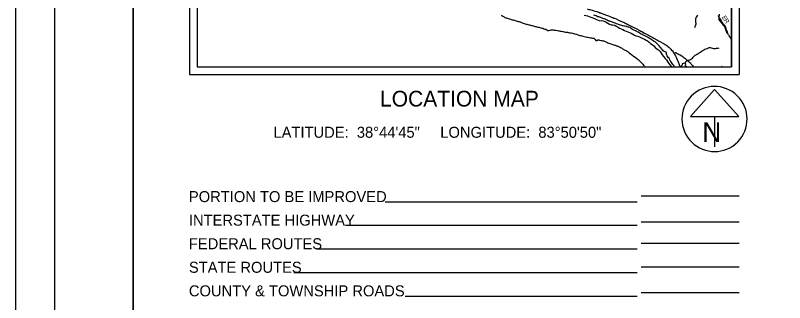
# Model space of a CAD drawing. Extents: x 0 to 34, y 0 to 22.
# Drawn here: x 0 to 9.79, y 11.1 to 14.75 of the extents above; entities that cross this region are included whole.
import ezdxf

# ---------------------------------------------------------------- set-up
doc = ezdxf.new("R2010")
doc.units = 0
for name, color, linetype in [('Default', 7, 'Continuous'), ('GM_X_Major_River', 7, 'Continuous'), ('GM_X_Minor_River', 7, 'Continuous'), ('GM_X_Township_Road', 7, 'Continuous'), ('GM_X_Township_Road_Text', 7, 'Continuous'), ('GM_X_US_Route', 7, 'Continuous'), ('SH_Border', 7, 'Continuous'), ('SH_Cut_Line', 7, 'Continuous'), ('SH_Data', 7, 'Continuous'), ('SH_Text', 7, 'Continuous')]:
    doc.layers.add(name, color=color, linetype=linetype)

msp = doc.modelspace()

# ---------------------------------------------------------------- linework, layer by layer
at = {"layer": 'Default'}
msp.add_lwpolyline([(7.2409, 14.7567), (7.2605, 14.7513), (7.2834, 14.7475), (7.3046, 14.7393), (7.3244, 14.7309), (7.3479, 14.7233), (7.3703, 14.7143), (7.3952, 14.7015), (7.4163, 14.6918), (7.4385, 14.6851), (7.4584, 14.687), (7.4818, 14.6833), (7.501, 14.6756), (7.52, 14.667), (7.5406, 14.6542), (7.5611, 14.6406), (7.5821, 14.635), (7.603, 14.6335), (7.6287, 14.628), (7.6487, 14.6172), (7.6713, 14.6052), (7.6906, 14.5923), (7.7101, 14.5815), (7.7299, 14.5723), (7.752, 14.5624), (7.7959, 14.545), (7.8174, 14.5359), (7.8368, 14.5262), (7.8575, 14.5129), (7.8787, 14.5014), (7.8985, 14.4932), (7.9208, 14.4887), (7.942, 14.4801), (7.9627, 14.471), (7.9861, 14.4585), (8.0071, 14.449), (8.0265, 14.44), (8.0454, 14.4281), (8.0661, 14.4119), (8.0855, 14.397), (8.1063, 14.3826), (8.1264, 14.3655), (8.1445, 14.3461), (8.1649, 14.328), (8.186, 14.314), (8.206, 14.2944), (8.2209, 14.2742), (8.2341, 14.2531), (8.249, 14.2305), (8.2693, 14.2063), (8.2877, 14.1863), (8.3015, 14.1672), (8.3143, 14.1469), (8.3277, 14.1258), (8.3467, 14.101), (8.3479, 14.0996), (9.1142, 14.0996), (9.1142, 17.7402)], dxfattribs=at)
at = {"layer": 'GM_X_Major_River'}
for points in [[(6.1819, 14.7546), (6.1936, 14.7506), (6.2045, 14.7444), (6.2195, 14.7348), (6.2316, 14.7286), (6.2414, 14.7243), (6.2512, 14.7211), (6.261, 14.7187), (6.2735, 14.7133), (6.2893, 14.7082), (6.2995, 14.7054), (6.3124, 14.7022), (6.3237, 14.6987), (6.3339, 14.6955), (6.3479, 14.6916), (6.3607, 14.688), (6.3743, 14.6833), (6.3872, 14.6793), (6.3977, 14.6762), (6.4102, 14.6741)], [(7.9535, 14.5239), (7.938, 14.5324), (7.9275, 14.5382), (7.9154, 14.5448), (7.9026, 14.5526), (7.8925, 14.558), (7.8826, 14.5619), (7.8698, 14.5647), (7.8562, 14.5736), (7.8427, 14.5844), (7.8318, 14.5917), (7.8201, 14.5987), (7.81, 14.6026), (7.8001, 14.6058), (7.7869, 14.609), (7.7763, 14.611), (7.7631, 14.6149), (7.751, 14.6181), (7.7374, 14.6201), (7.7272, 14.6222), (7.7174, 14.6246), (7.7015, 14.6289), (7.6909, 14.6321), (7.6769, 14.6375), (7.6668, 14.6415), (7.6528, 14.6462), (7.6426, 14.6497), (7.632, 14.6536), (7.6207, 14.6576), (7.609, 14.6619), (7.5988, 14.6662), (7.589, 14.6708), (7.5766, 14.6755), (7.5667, 14.6783), (7.5554, 14.6815), (7.5445, 14.6858), (7.5309, 14.6916), (7.5207, 14.697), (7.506, 14.7037), (7.4928, 14.7088), (7.4785, 14.7158), (7.4672, 14.7204), (7.4509, 14.7271), (7.4377, 14.731), (7.4271, 14.7334), (7.4147, 14.7359), (7.403, 14.7402), (7.3905, 14.746), (7.3766, 14.7515), (7.3637, 14.7554)], [(6.4102, 14.6741), (6.4238, 14.6709), (6.4495, 14.6608), (6.4631, 14.6549), (6.4763, 14.6498), (6.4865, 14.6471), (6.4997, 14.6435), (6.5099, 14.6407), (6.5227, 14.6375), (6.5333, 14.6351), (6.5447, 14.6327), (6.5564, 14.6299), (6.5681, 14.6268), (6.5787, 14.6244), (6.59, 14.6212), (6.6032, 14.6176), (6.6161, 14.6141), (6.6259, 14.6113), (6.638, 14.6081), (6.6508, 14.6046), (6.6614, 14.6018), (6.6739, 14.5994), (6.6886, 14.5961), (6.7003, 14.593), (6.712, 14.5894), (6.7271, 14.5843), (6.7396, 14.5804), (6.7524, 14.5764), (6.7649, 14.5706), (6.7777, 14.5629), (6.7913, 14.5597), (6.8046, 14.5663), (6.8191, 14.5707), (6.8312, 14.5698), (6.8441, 14.5685), (6.8562, 14.5669), (6.8698, 14.5652), (6.8796, 14.564), (6.8997, 14.5595), (6.911, 14.5571), (6.922, 14.5551), (6.9329, 14.5535), (6.9481, 14.5514), (6.9621, 14.5493), (6.9723, 14.5473), (6.9863, 14.5441), (7.0033, 14.5413), (7.0154, 14.5396), (7.0264, 14.538), (7.0392, 14.5352), (7.0521, 14.5331), (7.0634, 14.5315), (7.0744, 14.5298), (7.0895, 14.5266), (7.105, 14.5234), (7.1167, 14.5202), (7.1266, 14.5175), (7.142, 14.5127), (7.1598, 14.5072), (7.1707, 14.5037), (7.1855, 14.4997), (7.1987, 14.4961), (7.2104, 14.493), (7.2217, 14.4902), (7.238, 14.4866), (7.255, 14.4822), (7.2747, 14.4774), (7.2871, 14.4746), (7.303, 14.4721), (7.3181, 14.4693), (7.3321, 14.4669), (7.3473, 14.464), (7.3609, 14.462), (7.3707, 14.4569), (7.38, 14.4454), (7.3886, 14.4351), (7.4015, 14.4353), (7.4152, 14.4435), (7.4251, 14.4423), (7.4353, 14.4395), (7.4496, 14.4359), (7.4644, 14.4335), (7.4784, 14.431), (7.4882, 14.4283), (7.4988, 14.4247), (7.5139, 14.4185), (7.5263, 14.4123), (7.5395, 14.4064), (7.5535, 14.4013), (7.5678, 14.3958), (7.5799, 14.3915), (7.5912, 14.388), (7.6041, 14.3836), (7.6143, 14.3805), (7.6278, 14.3762), (7.6392, 14.3726), (7.6505, 14.3679), (7.6614, 14.364), (7.675, 14.3585), (7.689, 14.3523), (7.7025, 14.3461)], [(8.3892, 14.0996), (8.3865, 14.1037), (8.3787, 14.1155), (8.369, 14.1285), (8.3604, 14.1408), (8.3496, 14.155), (8.3421, 14.1645), (8.3358, 14.1767), (8.331, 14.1889), (8.3247, 14.2027), (8.3138, 14.215), (8.3045, 14.2249), (8.2955, 14.2372), (8.2896, 14.249), (8.2878, 14.2585), (8.2861, 14.2715), (8.2813, 14.2837), (8.2692, 14.291), (8.2567, 14.2919), (8.244, 14.3023), (8.2369, 14.3141), (8.2268, 14.3257), (8.2144, 14.3387), (8.2047, 14.351), (8.1976, 14.3617), (8.1894, 14.372), (8.1778, 14.3839), (8.1643, 14.397), (8.1523, 14.407), (8.141, 14.4151), (8.1289, 14.4228), (8.1161, 14.4306), (8.1037, 14.4379), (8.0928, 14.4452), (8.0815, 14.4533), (8.0687, 14.4618), (8.0575, 14.4688), (8.0454, 14.4758), (8.0292, 14.4843), (8.0013, 14.4987), (7.9908, 14.5034), (7.9791, 14.5096), (7.9667, 14.5165), (7.9535, 14.5239)], [(7.7025, 14.3461), (7.7146, 14.3395), (7.7262, 14.3299), (7.7387, 14.3221), (7.7496, 14.3163), (7.7605, 14.3124), (7.7722, 14.3062), (7.7831, 14.2988), (7.7993, 14.288), (7.8113, 14.2788), (7.8301, 14.263), (7.8421, 14.2537), (7.8519, 14.2468), (7.8651, 14.2383), (7.8797, 14.2275), (7.8899, 14.2198), (7.9038, 14.2094), (7.9158, 14.199), (7.9255, 14.1905), (7.9394, 14.1782), (7.9507, 14.1663), (7.9604, 14.1571), (7.9754, 14.1433), (7.9866, 14.131), (7.9964, 14.1206), (8.0068, 14.1061), (8.0113, 14.0996)]]:
    msp.add_lwpolyline(points, dxfattribs=at)
at = {"layer": 'GM_X_Minor_River'}
msp.add_line((8.9886, 14.0996), (8.9952, 14.1065), dxfattribs=at)
for points in [[(7.3861, 14.7477), (7.3929, 14.7618)], [(8.6798, 14.7552), (8.6732, 14.7424), (8.6658, 14.7303), (8.6599, 14.719), (8.6567, 14.7084), (8.6546, 14.6944), (8.6556, 14.6807), (8.6573, 14.6678), (8.6586, 14.6545), (8.6588, 14.6438), (8.6583, 14.6309), (8.6543, 14.6173), (8.6492, 14.6068), (8.6433, 14.5935)], [(8.9557, 14.7683), (8.9558, 14.7535), (8.9549, 14.7425), (8.954, 14.7311), (8.9541, 14.7167), (8.9544, 14.7049), (8.9576, 14.6934), (8.965, 14.6827), (8.9766, 14.6708), (8.9859, 14.6573), (8.9959, 14.6443), (9.0101, 14.6296), (9.0239, 14.6131), (9.0313, 14.5997), (9.0361, 14.5886), (9.0382, 14.5783), (9.0399, 14.5681), (9.0447, 14.5539), (9.0494, 14.541), (9.056, 14.5287)], [(8.5253, 14.1464), (8.5342, 14.166), (8.545, 14.1761), (8.5587, 14.1816), (8.5716, 14.1848), (8.5831, 14.1881), (8.5941, 14.1932), (8.606, 14.1999), (8.6175, 14.2085), (8.6276, 14.222), (8.6384, 14.2347), (8.6522, 14.2463), (8.6625, 14.2522), (8.6751, 14.2589), (8.6847, 14.2637), (8.6969, 14.2726), (8.7084, 14.2801), (8.718, 14.2864), (8.7279, 14.2919), (8.7421, 14.3004), (8.7559, 14.309), (8.7654, 14.3145), (8.7773, 14.3216), (8.7903, 14.3263), (8.8067, 14.3318), (8.8212, 14.3388), (8.8318, 14.3428), (8.8433, 14.3453), (8.8576, 14.3424), (8.8712, 14.3366), (8.8848, 14.3337), (8.8977, 14.3328), (8.9113, 14.3333), (8.9235, 14.3347), (8.9341, 14.3364), (8.9444, 14.3385), (8.9577, 14.3418)], [(8.5452, 14.0996), (8.5427, 14.1013), (8.5296, 14.1084), (8.5274, 14.1194), (8.5315, 14.1338), (8.5267, 14.1467), (8.5008, 14.1403), (8.4883, 14.1386), (8.4858, 14.1257), (8.4845, 14.1162), (8.4752, 14.1027), (8.4698, 14.0996)]]:
    msp.add_lwpolyline(points, dxfattribs=at)
at = {"layer": 'GM_X_Township_Road'}
for points in [[(9.1142, 14.4493), (9.1125, 14.4514), (9.0974, 14.4744), (9.086, 14.4914), (9.0787, 14.503), (9.0763, 14.5073), (9.0721, 14.5156), (9.0699, 14.5207), (9.0681, 14.526), (9.0656, 14.5356), (9.0642, 14.541), (9.0628, 14.5451), (9.0614, 14.5492), (9.059, 14.5549), (9.0557, 14.5616), (9.0518, 14.5694), (9.0489, 14.5756), (9.047, 14.5809), (9.0459, 14.5844), (9.0449, 14.588), (9.0413, 14.6037), (9.0404, 14.6074), (9.0389, 14.6111), (9.0371, 14.6144), (9.0347, 14.618), (9.0312, 14.6224), (9.0262, 14.6279), (9.02, 14.634), (9.0129, 14.641), (9.0088, 14.6456), (9.0054, 14.65), (9.0023, 14.6547), (8.9986, 14.6611), (8.9934, 14.671), (8.9886, 14.6797), (8.9858, 14.6845), (8.9789, 14.697), (8.9714, 14.7105), (8.9656, 14.7199), (8.9627, 14.7239), (8.9595, 14.728), (8.9551, 14.7338), (8.9523, 14.7386), (8.9511, 14.7421), (8.9504, 14.7445), (8.9496, 14.7494), (8.9492, 14.7543)], [(8.6353, 14.0996), (8.6289, 14.1057), (8.6218, 14.1126), (8.6091, 14.1253), (8.6011, 14.1331), (8.595, 14.1393), (8.5826, 14.1514), (8.5716, 14.1623), (8.5521, 14.1805), (8.5439, 14.188), (8.5332, 14.1974), (8.5094, 14.2154), (8.4937, 14.2255), (8.4616, 14.2456), (8.4499, 14.2526), (8.4376, 14.2599), (8.4202, 14.2704), (8.4149, 14.2738), (8.4097, 14.2764), (8.4042, 14.2779), (8.402, 14.2778), (8.3995, 14.2765), (8.395, 14.2739), (8.3854, 14.2685)]]:
    msp.add_lwpolyline(points, dxfattribs=at)
at = {"layer": 'GM_X_US_Route'}
for points in [[(7.281, 14.8353), (7.287, 14.8339), (7.3002, 14.8304), (7.312, 14.8274), (7.341, 14.8194), (7.3543, 14.8155), (7.3744, 14.8094), (7.3999, 14.8016), (7.4189, 14.7956), (7.4248, 14.7937), (7.44, 14.7883), (7.4482, 14.7852), (7.4598, 14.7807), (7.4754, 14.7747), (7.5004, 14.7652), (7.5195, 14.7581), (7.5482, 14.7475), (7.5882, 14.7321), (7.6049, 14.7254), (7.6165, 14.7204)], [(7.6165, 14.7204), (7.6209, 14.7185), (7.6255, 14.7165)], [(7.6255, 14.7165), (7.6449, 14.7082), (7.6755, 14.6945), (7.7377, 14.6661), (7.747, 14.6617)], [(7.747, 14.6617), (7.7489, 14.6608), (7.7634, 14.6539)], [(7.7634, 14.6539), (7.7725, 14.6496), (7.7949, 14.6388), (7.8394, 14.6168), (7.871, 14.6008), (7.9013, 14.5849), (7.9083, 14.5812)], [(7.9083, 14.5812), (7.9396, 14.5643), (7.9608, 14.553)], [(7.9608, 14.553), (7.9715, 14.5474), (8.0053, 14.529), (8.0581, 14.5), (8.0729, 14.4921), (8.1032, 14.4762), (8.125, 14.4642), (8.1645, 14.4434), (8.1864, 14.4316), (8.2099, 14.4189), (8.2414, 14.4013), (8.257, 14.3922), (8.2702, 14.384), (8.2806, 14.3771), (8.2922, 14.3687), (8.3055, 14.3584), (8.3151, 14.3504), (8.3238, 14.3425), (8.3337, 14.333), (8.3429, 14.3231), (8.3519, 14.3128), (8.3617, 14.3008), (8.3703, 14.2895), (8.3782, 14.2785), (8.3854, 14.2685)], [(8.3854, 14.2685), (8.395, 14.2513), (8.4025, 14.2375), (8.4101, 14.2221), (8.4155, 14.2101), (8.4276, 14.1814), (8.4352, 14.1625), (8.4482, 14.1305), (8.4612, 14.0996)]]:
    msp.add_lwpolyline(points, dxfattribs=at)
at = {"layer": 'SH_Border'}
for points in [[(0.5, 21.5), (1.5, 21.5), (1.5, 0.5), (0.5, 0.5)], [(1.5, 21.5), (33.5, 21.5), (33.5, 0.5), (1.5, 0.5)]]:
    msp.add_lwpolyline(points, close=True, dxfattribs=at)
at = {"layer": 'SH_Cut_Line'}
msp.add_lwpolyline([(0, 0), (34, 0), (34, 22), (0, 22)], close=True, dxfattribs=at)
msp.add_lwpolyline([(7.2409, 14.7567), (7.2605, 14.7513), (7.2834, 14.7475), (7.3046, 14.7393), (7.3244, 14.7309), (7.3479, 14.7233), (7.3703, 14.7143), (7.3952, 14.7015), (7.4163, 14.6918), (7.4385, 14.6851), (7.4584, 14.687), (7.4818, 14.6833), (7.501, 14.6756), (7.52, 14.667), (7.5406, 14.6542), (7.5611, 14.6406), (7.5821, 14.635), (7.603, 14.6335), (7.6287, 14.628), (7.6487, 14.6172), (7.6713, 14.6052), (7.6906, 14.5923), (7.7101, 14.5815), (7.7299, 14.5723), (7.752, 14.5624), (7.7959, 14.545), (7.8174, 14.5359), (7.8368, 14.5262), (7.8575, 14.5129), (7.8787, 14.5014), (7.8985, 14.4932), (7.9208, 14.4887), (7.942, 14.4801), (7.9627, 14.471), (7.9861, 14.4585), (8.0071, 14.449), (8.0265, 14.44), (8.0454, 14.4281), (8.0661, 14.4119), (8.0855, 14.397), (8.1063, 14.3826), (8.1264, 14.3655), (8.1445, 14.3461), (8.1649, 14.328), (8.186, 14.314), (8.206, 14.2944), (8.2209, 14.2742), (8.2341, 14.2531), (8.249, 14.2305), (8.2693, 14.2063), (8.2877, 14.1863), (8.3015, 14.1672), (8.3143, 14.1469), (8.3277, 14.1258), (8.3467, 14.101), (8.3479, 14.0996), (9.1142, 14.0996), (9.1142, 20.8996)], dxfattribs=at)
at = {"layer": 'SH_Data'}
for p, q in [((2.2142, 20.9996), (2.2142, 13.9996)), ((9.2142, 20.9996), (9.2142, 13.9996)), ((2.3142, 20.8996), (2.3142, 14.0996)), ((9.1142, 20.8996), (9.1142, 14.0996)), ((2.3142, 14.0996), (9.1142, 14.0996)), ((2.3142, 14.0996), (2.3142, 14.0996)), ((2.2142, 13.9996), (9.2142, 13.9996)), ((8.8987, 13.8086), (8.5911, 13.4674)), ((9.2063, 13.4674), (8.8987, 13.8086)), ((8.5911, 13.4674), (9.2063, 13.4674)), ((8.8987, 13.4674), (8.8987, 13.0806)), ((7.9642, 12.4549), (9.2142, 12.4549)), ((7.9142, 12.3762), (4.7079, 12.3762)), ((7.9142, 12.0762), (4.2037, 12.0762)), ((9.2142, 12.1203), (7.9642, 12.1203)), ((9.2142, 11.8486), (7.9642, 11.8486)), ((7.9142, 11.7762), (3.8334, 11.7762)), ((7.9142, 11.4762), (3.543, 11.4762)), ((9.2142, 11.5486), (7.9642, 11.5486)), ((7.9142, 11.1762), (4.9595, 11.1762)), ((9.2142, 11.2219), (7.9642, 11.2219))]:
    msp.add_line(p, q, dxfattribs=at)
msp.add_arc((8.8987, 13.4349), 0.4148, 129.77984, 129.76332, dxfattribs=at)

# ---------------------------------------------------------------- texts
at = {"layer": 'GM_X_Township_Road_Text'}
for s, rotation, p in [('E', 297.7718, (8.9901, 14.7326)), ('R', 304.09051, (9.0134, 14.6891))]:
    msp.add_text(s, height=0.0568, rotation=rotation, dxfattribs=at).set_placement(p)
at = {"layer": 'SH_Data'}
msp.add_text('N', height=0.25, dxfattribs=at).set_placement((8.7434, 13.1435))
at = {"layer": 'SH_Text'}
for s, height, p in [('LOCATION MAP', 0.2, (4.6412, 13.5933)), ('LATITUDE:  38°44\'45"     LONGITUDE:  83°50\'50"', 0.14, (3.2852, 13.1954)), ('PORTION TO BE IMPROVED', 0.14, (2.2086, 12.3762)), ('INTERSTATE HIGHWAY', 0.14, (2.2086, 12.0762)), ('FEDERAL ROUTES', 0.14, (2.2086, 11.7762)), ('STATE ROUTES', 0.14, (2.2086, 11.4762)), ('COUNTY & TOWNSHIP ROADS', 0.14, (2.2086, 11.1762))]:
    msp.add_text(s, height=height, dxfattribs=at).set_placement(p)

doc.saveas('drawing.dxf')
